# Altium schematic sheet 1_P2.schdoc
size 429 x 302 mm
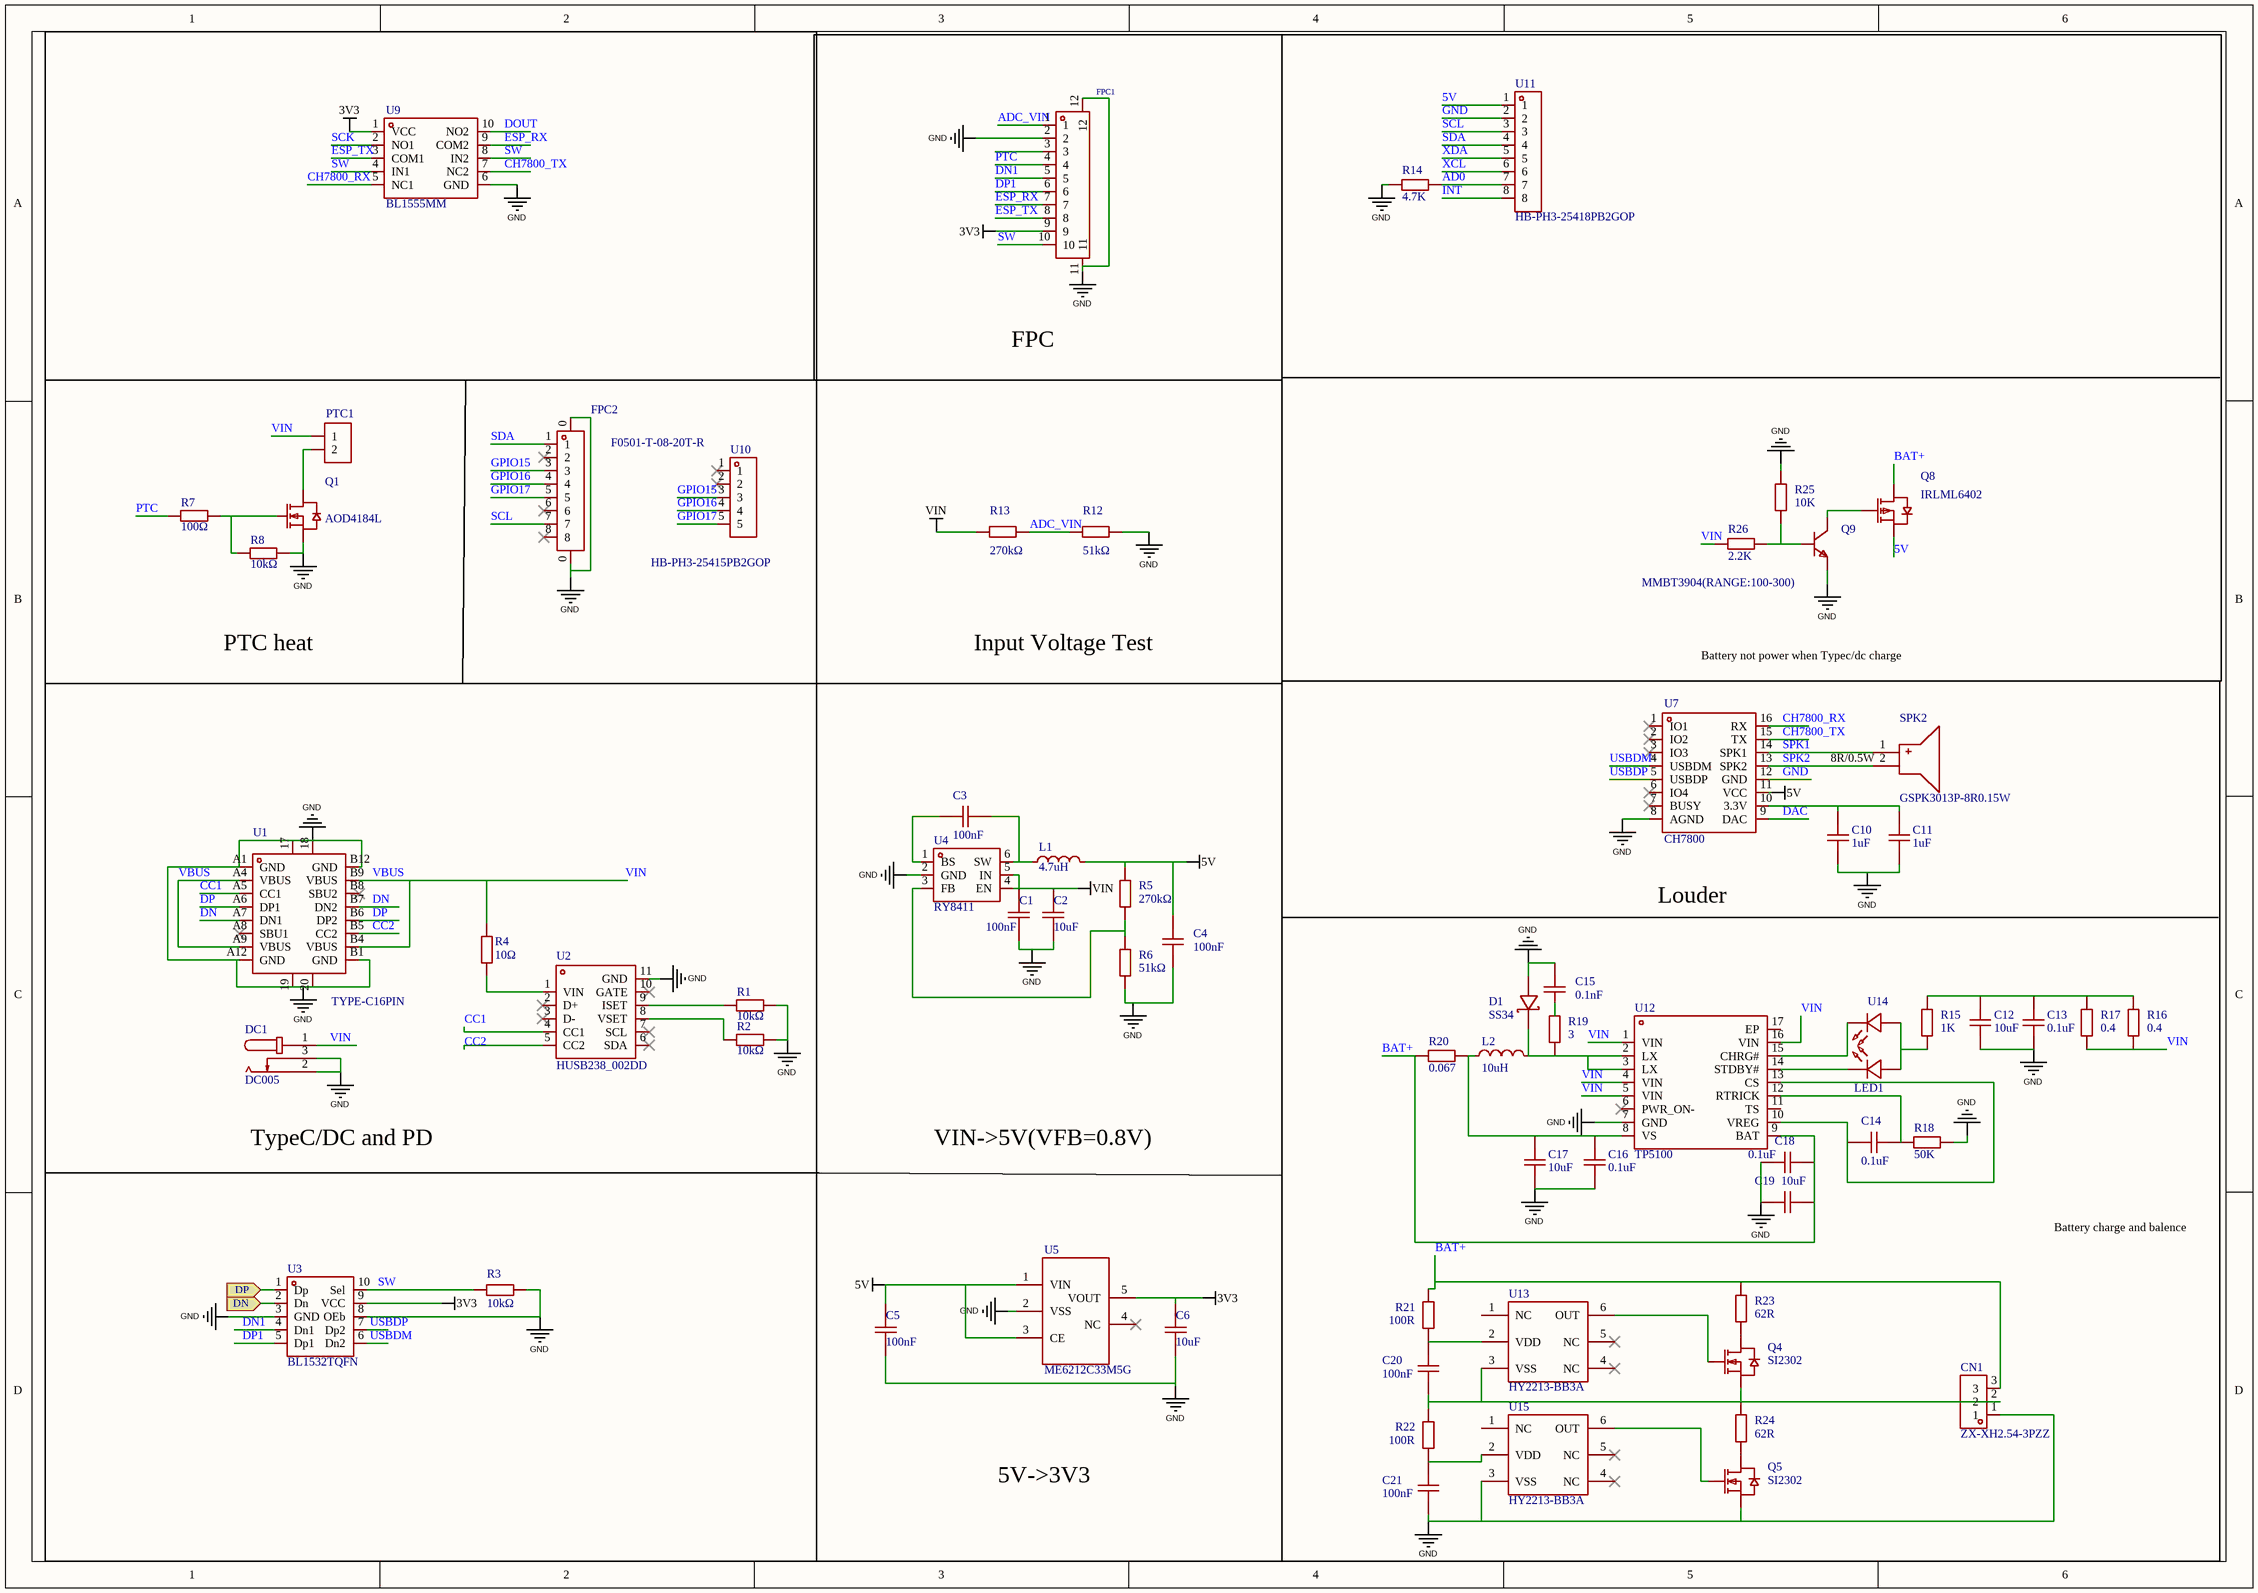
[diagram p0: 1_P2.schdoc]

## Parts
C1  100nF  [C0603]
C2  10uF  [C0603]
C3  100nF  [C0603]
C4  100nF  [C0603]
C5  100nF  [C0603]
C6  10uF  [C0603]
C10  1uF  [C0603]
C11  1uF  [C0603]
C12  10uF  [C0603]
C13  0.1uF  [C0603]
C14  0.1uF  [C0603]
C15  0.1nF  [C0603]
C16  0.1uF  [C0603]
C17  10uF  [C0603]
C18  0.1uF  [C0603]
C19  10uF  [C0603]
C20  100nF  [C0603]
C21  100nF  [C0603]
CN1  ZX-XH2.54-3PZZ  [CONN-TH_3P-P2.54_2501S-3P]
D1  SS34  [SMA_L4.3-W2.6-LS5.2-RD]
DC1  DC005  [DC-IN-TH_DC005]
FPC1  F0501-T-10-20T-R  [FPC-SMD_F0501-T-10-20T-R]  (value not drawn)
FPC2  F0501-T-08-20T-R  [FPC-SMD_8P-P0.50_L4.4-W9.6]
L1  4.7uH  [IND-SMD_L3.5-W3.0]
L2  10uH  [L0603]
LED1  XL-1608SURC-06  [LED0603-RD_RED]  (value not drawn)
PTC1  (no value)  [HDR-TH_2P-P2.54-V-F]
Q1  AOD4184L  [TO-252-2_L6.6-W6.1-P4.57-LS9.9-TL-CW]
Q4  SI2302  [SOT-23-3_L2.9-W1.3-P1.90-LS2.4-BR]
Q5  SI2302  [SOT-23-3_L2.9-W1.3-P1.90-LS2.4-BR]
Q8  IRLML6402  [SOT-23-3_L2.9-W1.3-P1.90-LS2.4-BR]
Q9  MMBT3904(RANGE:100-300)  [SOT-23-3_L2.9-W1.3-P1.90-LS2.4-BR]
R1  10kΩ  [R0603]
R2  10kΩ  [R0603]
R3  10kΩ  [R0603]
R4  10Ω  [R0603]
R5  270kΩ  [R0603]
R6  51kΩ  [R0603]
R7  100Ω  [R0603]
R8  10kΩ  [R0603]
R12  51kΩ  [R0603]
R13  270kΩ  [R0603]
R14  4.7K  [R0603]
R15  1K  [R0603]
R16  0.4  [R0603]
R17  0.4  [R0603]
R18  50K  [R0603]
R19  3  [R0603]
R20  0.067  [R0603]
R21  100R  [R0603]
R22  100R  [R0603]
R23  62R  [R0603]
R24  62R  [R0603]
R25  10K  [R0603]
R26  2.2K  [R0603]
SPK2  GSPK3013P-8R0.15W  [SPK-TH_BD30.0-P15.00-D0.8-L-RD]
U1  TYPE-C16PIN  [USB-C-SMD_TYPE-C16PIN]
U2  HUSB238_002DD  [DFN-10_L3.0-W3.0-P0.50-BL-EP2.5]
U3  BL1532TQFN  [QFN-10_L1.4-W1.8-P0.40-BL]
U4  RY8411  [SOT-23-6_L2.9-W1.6-P0.95-LS2.8-TL]
U5  ME6212C33M5G  [SOT-23-5_L3.0-W1.7-P0.95-LS2.8-BL]
U7  CH7800  [SOP-16_L9.9-W3.9-P1.27-LS6.0-BL]
U9  BL1555MM  [MSOP-10_L3.0-W3.0-P0.50-LS5.0-BL]
U10  HB-PH3-25415PB2GOP  [HDR-TH_5P-P2.54-V-M]
U11  HB-PH3-25418PB2GOP  [HDR-TH_8P-P2.54-V-M]
U12  TP5100  [TQFN-16_L4.0-W4.0-P0.65-BL-EP]
U13  HY2213-BB3A  [SOT-23-6_L2.9-W1.6-P0.95-LS2.8-BR]
U14  42-51/GHC-YW2X2K/3T  [LED-SMD_L1.6-W0.8-FD_GREEN-1]  (value not drawn)
U15  HY2213-BB3A  [SOT-23-6_L2.9-W1.6-P0.95-LS2.8-BR]

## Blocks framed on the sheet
FPC: FPC1
Battery not power when Typec/dc charge: Q8 Q9 R14 R25 R26 U11
PTC heat: FPC2 PTC1 Q1 R7 R8 U10
Input Voltage Test: R12 R13
TypeC/DC and PD: DC1 R1-R4 U1-U3
Louder: C10-C21 CN1 D1 L2 LED1 Q4 Q5 R15-R24 SPK2 U7 U12-U15

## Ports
DN (in), DP (in)

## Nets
3V3: C6.1 FPC1.9 U3.9(VCC) U5.5(VOUT) U9.1(VCC)
5V: C4.1 C5.1 L1.2 Q8.2(S) R5.2 U5.1(VIN) U5.3(CE) U7.11(VCC) U11.1
GND: C1.2 C2.2 C4.2 C5.2 C6.2 C10.1 C11.1 C12.1 C13.1 C15.2 C16.1 C17.1 C18.2 C19.2 C21.1 CN1.1 D1.2(A) DC1.2 DC1.3 FPC1.2 FPC1.11 FPC1.12 FPC2.0 Q1.3(S) Q5.2(S) Q9.2(E) R1.2 R2.2 R3.1 R6.1 R8.2 R12.2 R14.1 R18.2 R25.2 U1.17 U1.18 U1.19 U1.20 U1.A1(GND) U1.A12(GND) U1.B1(GND) U1.B12(GND) U2.11(GND) U3.3(GND) U3.8(OEb) U4.2(GND) U5.2(VSS) U7.8(AGND) U7.12(GND) U9.6(GND) U11.2 U12.7(GND) U15.3(VSS)
VBUS: C1.1 C2.1 DC1.1 PTC1.1 R4.2 R13.1 R16.1 R17.1 R26.1 U1.A4(VBUS) U1.A9(VBUS) U1.B4(VBUS) U1.B9(VBUS) U4.4(EN) U4.5(IN) U12.1(VIN) U12.4(VIN) U12.5(VIN) U12.16(VIN)  [also labelled VIN]
AD0: R14.2 U11.7
ADC_VIN: FPC1.1 R12.1 R13.2
BAT+: C18.1 C19.1 CN1.3 Q8.3(D) R20.1 R21.2 R23.2 U12.9(BAT)
CC1: U1.A5(CC1) U2.4(CC1)
CC2: U1.B5(CC2) U2.5(CC2)
CH7800_RX: U7.16(RX) U9.5(NC1)
CH7800_TX: U7.15(TX) U9.7(NC2)
DAC: U7.9(DAC)
DN: U3.2(Dn) ; port DN
DN: U1.A7(DN1) U1.B7(DN2)  [a separate net that carries the same name]
DN1: FPC1.5 U3.4(Dn1)
DOUT: U9.10(NO2)
DP: U3.1(Dp) ; port DP
DP: U1.A6(DP1) U1.B6(DP2)  [a separate net that carries the same name]
DP1: FPC1.6 U3.5(Dp1)
ESP_RX: FPC1.7 U9.9(COM2)
ESP_TX: FPC1.8 U9.3(COM1)
GPIO15: FPC2.3 U10.3
GPIO16: FPC2.4 U10.4
GPIO17: FPC2.5 U10.5
INT: U11.8
PTC: FPC1.4 R7.1
SCK: U9.2(NO1)
SCL: FPC2.7 U11.3
SDA: FPC2.1 U11.4
SPK1: SPK2.1(+) U7.14(SPK1)
SPK2: SPK2.2(-) U7.13(SPK2)
SW: FPC1.10 R3.2 U3.10(Sel) U9.4(IN1) U9.8(IN2)
USBDM: U3.6(Dn2) U7.4(USBDM)
USBDP: U3.7(Dp2) U7.5(USBDP)
XCL: U11.6
XDA: U11.5
NetC3_1: C3.1 U4.1(BS)
NetC3_2: C3.2 L1.1 U4.6(SW)
NetC10_2: C10.2 C11.2 U7.10(3.3V)
NetC12_2: C12.2 C13.2 R15.2 R16.2 R17.2
NetC14_1: C14.1 U12.10(VREG) U12.13(CS)
NetC14_2: C14.2 R18.1 U12.12(RTRICK)
NetC15_1: C15.1 R19.2
NetC16_2: C16.2 C17.2 L2.1 R20.2 U12.8(VS)
NetC20_1: C20.1 CN1.2 Q4.2(S) R22.2 R24.2 U13.3(VSS)
NetC20_2: C20.2 R21.1 U13.2(VDD)
NetC21_2: C21.2 R22.1 U15.2(VDD)
NetD1_1: D1.1(K) L2.2 R19.1 U12.2(LX) U12.3(LX)
NetLED1_1: LED1.1(K) U12.14(STDBY#)
NetLED1_2: LED1.2(A) R15.1 U14.1(A)
NetPTC1_2: PTC1.2 Q1.2(D)
NetQ1_1: Q1.1(G) R7.2 R8.1
NetQ4_1: Q4.1(G) U13.6(OUT)
NetQ4_3: Q4.3(D) R23.1
NetQ5_1: Q5.1(G) U15.6(OUT)
NetQ5_3: Q5.3(D) R24.1
NetQ8_1: Q8.1(G) Q9.3(C)
NetQ9_1: Q9.1(B) R25.1 R26.2
NetR1_1: R1.1 U2.9(ISET)
NetR2_1: R2.1 U2.8(VSET)
NetR4_1: R4.1 U2.1(VIN)
NetR5_1: R5.1 R6.2 U4.3(FB)
NetU12_15: U12.15(CHRG#) U14.2(C)

Not connected (* = marked no-connect by the designer): FPC1 3; FPC2 2* 6* 8*; U1 A8(SBU1)* B8(SBU2)*; U2 2(D+)* 3(D-)* 6(SDA)* 7(SCL)* 10(GATE)*; U5 4(NC)*; U7 1(IO1)* 2(IO2)* 3(IO3)* 6(IO4)* 7(BUSY)*; U10 1* 2*; U12 6(PWR_ON-)* 11(TS) 17(EP); U13 1(NC) 4(NC)* 5(NC)*; U15 1(NC) 4(NC)* 5(NC)*

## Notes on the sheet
- (near SPK2) 8R/0.5W
- VIN->5V(VFB=0.8V)
- Battery charge and balence
- 5V->3V3

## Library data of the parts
C1 C3-C5 = CGA0603X7R104K500JT: Manufacturer: HRE(芯声); Symbol: CapAcitance; Add into BOM: yes; Tolerance: ±10%; Voltage Rated: 50V; Temperature Coefficient: X7R
C2 C6 = CL10A106KP8NNNC: Manufacturer: SAMSUNG(三星); Symbol: CapAcitance; Add into BOM: yes; Tolerance: ±10%; Voltage Rated: 10V; Temperature Coefficient: X5R
C10 C11 = CL10A105KA8NNNC: Manufacturer: SAMSUNG(三星); Symbol: CapAcitance; Add into BOM: yes; Tolerance: ±10%; Voltage Rated: 25V; Temperature Coefficient: X5R
C12-C21 = CAP_0603: Symbol: CapAcitance; Convert to PCB: yes
CN1 = ZX-XH2.54-3PZZ: Manufacturer: Megastar(兆星); Add into BOM: yes; Pins Structure: 1x3P; Pitch: 2.5mm; Reference Series: XH; Number of PINs Per Row: 3; Rated Current: 3A; Rated Voltage (Max): 250V; Plastic Material: PA66; Flame Retardant Rating: UL94V-0; Z-Height of the Board: 7mm; X-Length of Bottom Edge on Board (Spacing Line): 10mm; Y-Width of Bottom Edge on Board: 5.9mm
D1 = SS34_C8678: Manufacturer: MDD(辰达半导体); Add into BOM: yes; Diode Configuration: 独立式; Forward Voltage (Vf@If): 550mV@3A; Reverse Voltage (Vr): 40V; Rectified Current: 3A; Reverse Leakage Current (Ir): 500uA@40V
DC1 = DC005: Manufacturer: SHOU HAN(首韩); Symbol: DC005_C431533; Add into BOM: yes; Connector Type: DC电源插座; Inside Contact Diameter: 2mm; Outside Contact Diameter: 6.3mm; Current Rating (Max): 500mA; Voltage Rating (Max): 30V
FPC1 = F0501-T-10-20T-R: Manufacturer: XFCN(兴飞); Add into BOM: yes; Pitch: 0.5mm; Number of Contacts: 10P; Locking Feature: 抽屉式
FPC2 = F0501-T-08-20T-R: Manufacturer: XFCN(兴飞); Add into BOM: yes; Locking Feature: 抽屉式; Number of Contacts: 8P; Pitch: 0.5mm
L1 = CD32-4R7M 4.7UH: Manufacturer: DMBJ(振宝佳); Add into BOM: yes; Tolerance: ±20%; Rated Current: 1.5A; DC Resistance (DCR): 137mΩ
L2 = L_0603: Symbol: SDFL1608S100KTF; Add into BOM: yes
LED1 = XL-1608SURC-06: Manufacturer: XINGLIGHT(成兴光); Add into BOM: yes; Illumination Color: 红色; Voltage - Forward(Vf): 2.3V; Power(Watts): 50mW; Forward Current: 20mA; Wavelength - Dominant: 620nm~630nm; Peak Wavelength: 625nm; Lens Color: 无色透明透镜; Luminous Intensity: 225mcd; Viewing Angle: 120°; Mounting Sytle: 正贴
PTC1 = HDR-F_2.54_1x2P: Manufacturer: BOOMELE(博穆精密); Manufacturer Part: 2.54-1*2P母; Symbol: Header-Female-2.54_1x2; Convert to PCB: yes
Q1 = AOD4184L: Manufacturer: AOS; Add into BOM: yes; Type: 1个N沟道; Drain Source Voltage (Vdss): 40V; Continuous Drain Current (Id): 50A; Drain Source On Resistance (RDS(on)@Vgs,Id): 8mΩ@10V,20A; Power Dissipation (Pd): 50W; Gate Threshold Voltage (Vgs(th)@Id): 3V@250uA
Q4 Q5 = SI2302_C2891732: Manufacturer: YONGYUTAI(永裕泰); Add into BOM: yes; Type: 1个N沟道; Drain Source Voltage (Vdss): 20V; Continuous Drain Current (Id): 3A; Drain Source On Resistance (RDS(on)@Vgs,Id): 50mΩ@4.5V,3A; Power Dissipation (Pd): 1W; Gate Threshold Voltage (Vgs(th)@Id): 1V@250uA; Total Gate Charge (Qg@Vgs): 60nC@4.5V; Input Capacitance (Ciss@Vds): 300pF@10V; Reverse Transfer Capacitance (Crss@Vds): 80pF@10V
Q8 = IRLML6402_C518785: Manufacturer: HUASHUO(华朔); Add into BOM: yes; Type: 1个P沟道; Drain Source Voltage (Vdss): 20V; Continuous Drain Current (Id): 4.9A; Drain Source On Resistance (RDS(on)@Vgs,Id): 45mΩ@4.5V,4.9A; Power Dissipation (Pd): 1.31W; Gate Threshold Voltage (Vgs(th)@Id): 400mV@250uA; Total Gate Charge (Qg@Vgs): 14.3nC@4.5V; Input Capacitance (Ciss@Vds): 1.2nF@15V; Reverse Transfer Capacitance (Crss@Vds): 151pF@15V
Q9 = MMBT3904(RANGE:100-300): Manufacturer: CJ(江苏长电/长晶); Add into BOM: yes; Transistor Type: NPN; Collector Current (Ic): 200mA; Collector-Emitter Breakdown Voltage (Vceo): 40V; Power Dissipation (Pd): 200mW; DC Current Gain (hFE@Ic,Vce): 100@10mA,1V; Transition Frequency (fT): 300MHz; Collector Cut-Off Current (Icbo): 100nA; Collector-Emitter Saturation Voltage (VCE(sat)@Ic,Ib): 300mV@50mA,5mA
R1-R3 R8 = 0603WAF1002T5E: Manufacturer: UNI-ROYAL(厚声); Symbol: 电阻; Add into BOM: yes; Tolerance: ±1%; Power(Watts): 100mW; Overload Voltage (Max): 75V; Temperature Coefficient: ±100ppm/℃
R4 = 0603WAF100JT5E: Manufacturer: UNI-ROYAL(厚声); Symbol: 电阻; Add into BOM: yes; Tolerance: ±1%; Power(Watts): 100mW; Overload Voltage (Max): 75V; Temperature Coefficient: ±400ppm/℃
R5 = FRC0603F2703TS: Manufacturer: FOJAN(富捷); Symbol: 电阻; Add into BOM: yes; Tolerance: ±1%; Power(Watts): 100mW; Overload Voltage (Max): 75V; Temperature Coefficient: ±100ppm/℃
R6 R12 = 0603WAF5102T5E: Manufacturer: UNI-ROYAL(厚声); Symbol: 电阻; Add into BOM: yes; Tolerance: ±1%; Power(Watts): 100mW; Overload Voltage (Max): 75V; Temperature Coefficient: ±100ppm/℃
R7 = 0603WAF1000T5E: Manufacturer: UNI-ROYAL(厚声); Symbol: 电阻; Add into BOM: yes; Tolerance: ±1%; Power(Watts): 100mW; Overload Voltage (Max): 75V; Temperature Coefficient: ±200ppm/℃
R13 = 0603WAF2703T5E: Manufacturer: UNI-ROYAL(厚声); Symbol: 电阻; Add into BOM: yes; Tolerance: ±1%; Power(Watts): 100mW; Overload Voltage (Max): 75V; Temperature Coefficient: ±100ppm/℃
R14-R26 = Res_0603: Symbol: 电阻; Convert to PCB: yes
SPK2 = GSPK3013P-8R0.15W: Manufacturer: INGHAi(赢海); Add into BOM: yes
U1 = TYPE-C16PIN: Manufacturer: SHOU HAN(首韩); Symbol: TYPE-C16PIN母座 板上四脚三次MOLDING; Add into BOM: yes; Connector Type: Type-C; Gender: 母; Number of Contacts: 16P; Number of Ports: 1; Current Rating - Power (Max): 3A; Rated Voltage (Max): 30V; Connect-Disconnect Life: 1万次; Core Colour: 黑色
U2 = HUSB238_002DD: Manufacturer: Hynetek(慧能泰); Symbol: HUSB238-002D; Add into BOM: yes
U3 = BL1532TQFN: Manufacturer: BL(上海贝岭); Add into BOM: yes
U4 = RY8411_C2935411: Manufacturer: RYCHiP(蕊源); Add into BOM: yes
U5 = ME6212C33M5G: Manufacturer: MICRONE(南京微盟); Add into BOM: yes; Output Type: 固定; Maximum Input Voltage: 6V; Output Voltage: 3.3V; MAX Output Current: 350mA; Power Supply Rejection Ratio (PSRR): 65dB; Dropout Voltage: 260mV@(200mA); Output Polarity: 正极; Number of Outputs: 1
U7 = CH7800: Add into BOM: yes
U9 = BL1555MM: Manufacturer: BL(上海贝岭); Add into BOM: yes
U10 = HB-PH3-25415PB2GOP: Manufacturer: HANBO(汉博); Add into BOM: yes; Pin Structure: 1x5P; Pitch: 2.54mm; Circluar Pins/Square Pins: 方针; Current Rating (Max): 3A; Voltage Rating (Max): 250V; Soldering Temperature(Max): 260℃
U11 = HB-PH3-25418PB2GOP: Manufacturer: HANBO(汉博); Add into BOM: yes; Pin Structure: 1x8P; Pitch: 2.54mm; Circluar Pins/Square Pins: 方针; Current Rating (Max): 3A; Voltage Rating (Max): 250V; Soldering Temperature(Max): 260℃
U12 = TP5100: Manufacturer: TOPPOWER(南京拓微); Symbol: TP5100_C379389; Add into BOM: yes
U13 U15 = HY2213-BB3A: Manufacturer: HYCON(宏康); Add into BOM: yes
U14 = 42-51/GHC-YW2X2K/3T: Manufacturer: EVERLIGHT(亿光); Add into BOM: yes; Emitted Color: 翠绿色; Dominant Wavelength: 520nm~535nm; Luminous Intensity: 2850mcd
